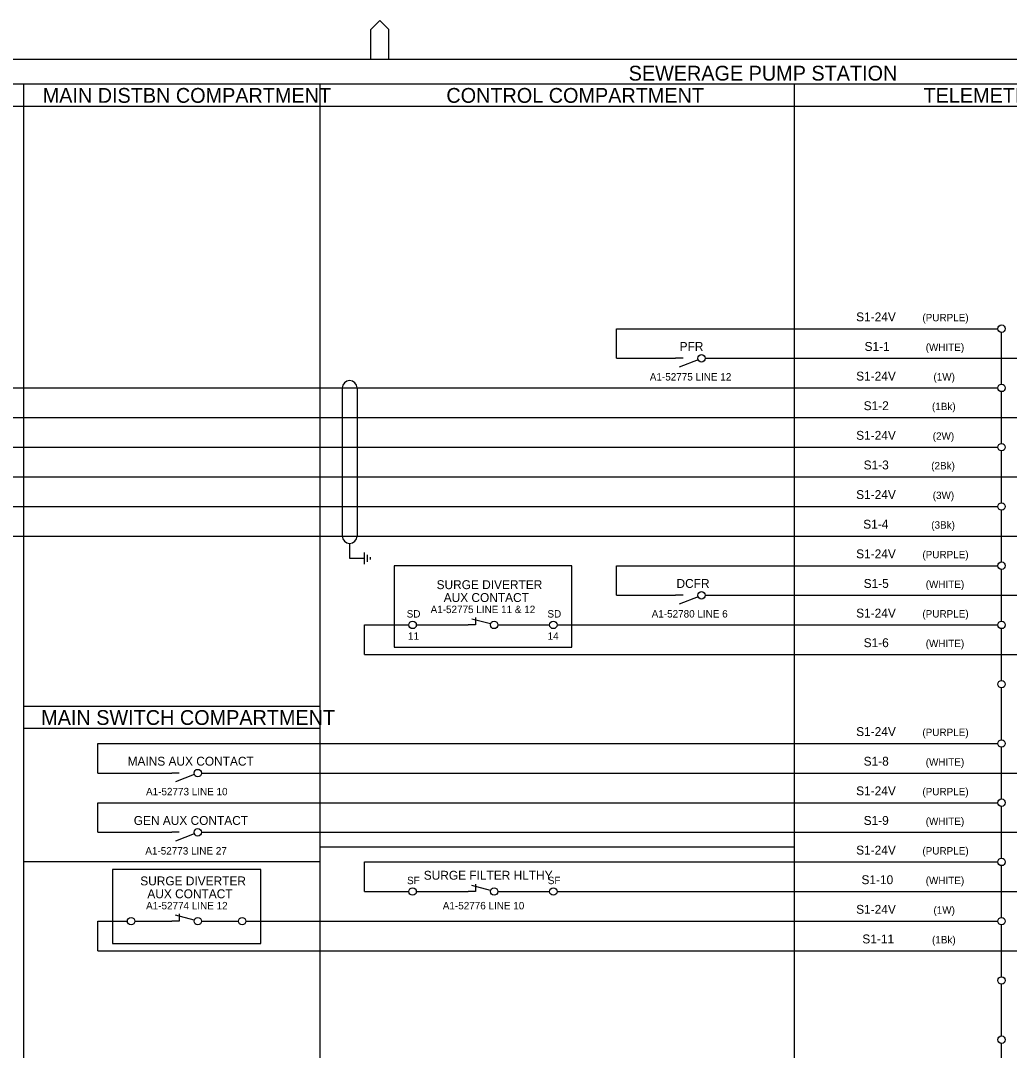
# Model space of a CAD drawing. Extents: x 0 to 841, y 0 to 594.
# Drawn here: x 299 to 632.6, y 246.4 to 594 of the extents above; entities that cross this region are included whole.
import ezdxf

# ---------------------------------------------------------------- set-up
doc = ezdxf.new("R2010")
doc.units = 0
for name, color, linetype in [('A1BORDER', 7, 'Continuous'), ('Level 1', 7, 'Continuous'), ('Level 10', 7, 'Continuous'), ('Level 5', 7, 'Continuous'), ('Level 6', 7, 'Continuous')]:
    doc.layers.add(name, color=color, linetype=linetype)

msp = doc.modelspace()

# ---------------------------------------------------------------- linework, layer by layer
at = {"layer": 'A1BORDER'}
for p, q in [((417.19, 591), (420.19, 594)), ((417.19, 581), (417.19, 591)), ((423.19, 591), (420.19, 594)), ((423.19, 581), (423.19, 591)), ((28, 581), (829, 581))]:
    msp.add_line(p, q, dxfattribs=at)
at = {"layer": 'Level 1'}
for p, q in [((829, 572.5), (160, 572.5)), ((300, 572.5), (300, 57)), ((400, 572.5), (400, 57)), ((560, 572.5), (560, 57)), ((829, 565), (160, 565)), ((500, 490), (628.75, 490)), ((500, 480), (500, 490)), ((630, 471.25), (630, 488.75)), ((500, 480), (520, 480)), ((522.5, 480), (520, 480)), ((520, 480), (520, 480)), ((530, 480), (685, 480)), ((530, 480), (530, 480)), ((280, 470), (628.75, 470)), ((407.5, 470), (407.5, 420)), ((412.5, 470), (412.5, 420)), ((630, 451.25), (630, 468.75)), ((280, 460), (685, 460)), ((280, 450), (628.75, 450)), ((630, 431.25), (630, 448.75)), ((280, 440), (685, 440)), ((280, 430), (628.75, 430)), ((630, 411.25), (630, 428.75)), ((280, 420), (685, 420)), ((410, 417.5), (410, 412.5)), ((410, 412.5), (415, 412.5)), ((500, 410), (628.75, 410)), ((500, 400), (500, 410)), ((630, 391.25), (630, 408.75)), ((500, 400), (520, 400)), ((522.5, 400), (520, 400)), ((520, 400), (520, 400)), ((530, 400), (685, 400)), ((530, 400), (530, 400)), ((415, 390), (430, 390)), ((415, 380), (415, 390)), ((432.5, 390), (450, 390)), ((452.5, 390), (450, 390)), ((480, 390), (628.75, 390)), ((630, 371.25), (630, 388.75)), ((415, 380), (685, 380)), ((630, 351.25), (630, 368.75)), ((400, 362.5), (300, 362.5)), ((400, 355), (300, 355)), ((325, 350), (628.75, 350)), ((325, 340), (325, 350)), ((630, 331.25), (630, 348.75)), ((325, 340), (350, 340)), ((352.5, 340), (350, 340)), ((350, 340), (350, 340)), ((360, 340), (685, 340)), ((360, 340), (360, 340)), ((325, 330), (628.75, 330)), ((325, 320), (325, 330)), ((630, 311.25), (630, 328.75)), ((325, 320), (350, 320)), ((352.5, 320), (350, 320)), ((350, 320), (350, 320)), ((360, 320), (685, 320)), ((360, 320), (360, 320)), ((560, 315), (400, 315)), ((400, 310), (300, 310)), ((415, 310), (628.75, 310)), ((415, 300), (415, 310)), ((630, 291.25), (630, 308.75)), ((415, 300), (430, 300)), ((432.5, 300), (450, 300)), ((452.5, 300), (450, 300)), ((480, 300), (685, 300)), ((325, 290), (335, 290)), ((325, 280), (325, 290)), ((337.5, 290), (350, 290)), ((352.5, 290), (350, 290)), ((375, 290), (628.75, 290)), ((630, 271.25), (630, 288.75)), ((325, 280), (685, 280)), ((630, 251.25), (630, 268.75)), ((630, 231.25), (630, 248.75))]:
    msp.add_line(p, q, dxfattribs=at)
for points in [[(425, 382.5), (485, 382.5), (485, 410), (425, 410)], [(330, 282.5), (380, 282.5), (380, 307.5), (330, 307.5)]]:
    msp.add_lwpolyline(points, close=True, dxfattribs=at)
for centre, start, end in [((410, 470), 0, 180), ((410, 420), 180, 0)]:
    msp.add_arc(centre, 2.5, start, end, dxfattribs=at)
at = {"layer": 'Level 10'}
for p, q in [((527.59, 479.54), (521.25, 477)), ((415, 410.5), (415, 414.5)), ((416, 411.3), (416, 413.7)), ((417, 412.1), (417, 412.9)), ((527.59, 399.54), (521.25, 397)), ((457.54, 390.32), (451.25, 392)), ((452.5, 392.5), (452.5, 390)), ((357.59, 339.54), (351.25, 337)), ((357.59, 319.54), (351.25, 317)), ((452.5, 302.5), (452.5, 300)), ((457.54, 300.32), (451.25, 302)), ((357.54, 290.32), (351.25, 292)), ((352.5, 292.5), (352.5, 290))]:
    msp.add_line(p, q, dxfattribs=at)
for centre in [(630, 490), (528.75, 480), (630, 470), (630, 450), (630, 430), (630, 410), (528.75, 400), (458.75, 390), (630, 390), (630, 370), (630, 350), (358.75, 340), (630, 330), (358.75, 320), (630, 310), (458.75, 300), (358.75, 290), (630, 290), (630, 270), (630, 250)]:
    msp.add_circle(centre, 1.25, dxfattribs=at)
at = {"layer": 'Level 5'}
for centre in [(431.25, 390), (478.75, 390), (431.25, 300), (478.75, 300), (336.25, 290), (373.75, 290)]:
    msp.add_circle(centre, 1.25, dxfattribs=at)
at = {"layer": 'Level 6'}
for p, q in [((460, 390), (477.5, 390)), ((460, 300), (477.5, 300)), ((360, 290), (372.5, 290))]:
    msp.add_line(p, q, dxfattribs=at)

# ---------------------------------------------------------------- texts
at = {"layer": 'Level 1'}
for s, height, p in [('SEWERAGE PUMP STATION', 5, (504.16, 573.75)), ('MAIN DISTBN COMPARTMENT', 5, (306.42, 566.25)), ('CONTROL COMPARTMENT', 5, (442.65, 566.25)), ('TELEMETRY COMPARTMENT', 5, (603.66, 566.25)), ('S1-24V', 3, (580.93, 492.5)), ('(PURPLE)', 2.5, (603.28, 492.5)), ('S1-1', 3, (583.76, 482.5)), ('(WHITE)', 2.5, (604.39, 482.5)), ('S1-24V', 3, (580.93, 472.5)), ('(1W)', 2.5, (607.01, 472.5)), ('S1-2', 3, (583.46, 462.5)), ('(1Bk)', 2.5, (606.51, 462.5)), ('S1-24V', 3, (580.93, 452.5)), ('(2W)', 2.5, (606.76, 452.5)), ('S1-3', 3, (583.46, 442.5)), ('(2Bk)', 2.5, (606.26, 442.5)), ('S1-24V', 3, (580.93, 432.5)), ('(3W)', 2.5, (606.76, 432.5)), ('S1-4', 3, (583.31, 422.5)), ('(3Bk)', 2.5, (606.26, 422.5)), ('S1-24V', 3, (580.93, 412.5)), ('(PURPLE)', 2.5, (603.28, 412.5)), ('S1-5', 3, (583.46, 402.5)), ('(WHITE)', 2.5, (604.4, 402.5)), ('SD', 2.5, (429.26, 392.5)), ('SD', 2.5, (476.76, 392.5)), ('S1-24V', 3, (580.93, 392.5)), ('(PURPLE)', 2.5, (603.28, 392.5)), ('S1-6', 3, (583.46, 382.5)), ('(WHITE)', 2.5, (604.4, 382.5)), ('MAIN SWITCH COMPARTMENT', 5, (305.92, 356.25)), ('S1-24V', 3, (580.93, 352.5)), ('(PURPLE)', 2.5, (603.28, 352.5)), ('S1-8', 3, (583.46, 342.5)), ('(WHITE)', 2.5, (604.4, 342.5)), ('S1-24V', 3, (580.93, 332.5)), ('(PURPLE)', 2.5, (603.28, 332.5)), ('S1-9', 3, (583.46, 322.5)), ('(WHITE)', 2.5, (604.4, 322.5)), ('S1-24V', 3, (580.93, 312.5)), ('(PURPLE)', 2.5, (603.28, 312.5)), ('SF', 2.5, (429.38, 302.5)), ('SF', 2.5, (476.88, 302.5)), ('S1-10', 3, (582.72, 302.5)), ('(WHITE)', 2.5, (604.4, 302.5)), ('S1-24V', 3, (580.93, 292.5)), ('(1W)', 2.5, (607.01, 292.5)), ('S1-11', 3, (583.02, 282.5)), ('(1Bk)', 2.5, (606.52, 282.5))]:
    msp.add_text(s, height=height, dxfattribs=at).set_placement(p)
at = {"layer": 'Level 5'}
for s, height, p in [('PFR', 3, (521.36, 482.5)), ('A1-52775 LINE 12', 2.5, (511.3, 472.5)), ('SURGE DIVERTER', 3, (439.35, 402.09)), ('DCFR', 3, (520.31, 402.5)), ('AUX CONTACT', 3, (441.74, 397.75)), ('A1-52775 LINE 11 & 12', 2.5, (437.33, 394)), ('A1-52780 LINE 6', 2.5, (511.93, 392.5)), ('11', 2.5, (429.69, 385)), ('14', 2.5, (476.81, 385)), ('MAINS AUX CONTACT', 3, (335.07, 342.5)), ('A1-52773 LINE 10', 2.5, (341.3, 332.5)), ('GEN AUX CONTACT', 3, (337.16, 322.5)), ('A1-52773 LINE 27', 2.5, (341.06, 312.5)), ('SURGE FILTER HLTHY', 3, (435.02, 304)), ('SURGE DIVERTER', 3, (339.35, 302.09)), ('AUX CONTACT', 3, (341.74, 297.75)), ('A1-52774 LINE 12', 2.5, (341.32, 294)), ('A1-52776 LINE 10', 2.5, (441.44, 294))]:
    msp.add_text(s, height=height, dxfattribs=at).set_placement(p)

doc.saveas('drawing.dxf')
